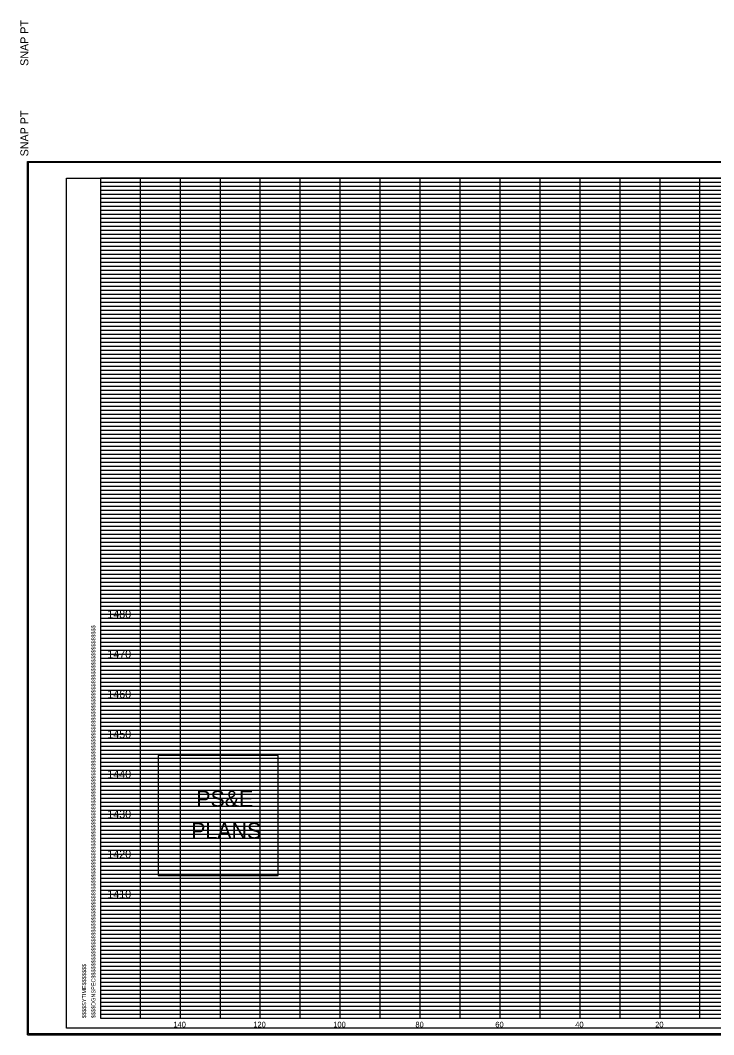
# Model space of a CAD drawing. Extents: x 980 to 2064, y 978 to 2267.
# Drawn here: x 979.9 to 1153.4, y 1255.9 to 1509.4 of the extents above; entities that cross this region are included whole.
import ezdxf

# ---------------------------------------------------------------- set-up
doc = ezdxf.new("R2010")
doc.units = 0
for name, color, linetype in [('Default', 7, 'Continuous'), ('DESIGN - SHEET - Corner Text', 7, 'Continuous'), ('DESIGN - SHEET - Light Grid', 7, 'Continuous'), ('DESIGN - SHEET - Linework', 7, 'Continuous'), ('DESIGN - SHEET - Plot Shape', 7, 'Continuous')]:
    doc.layers.add(name, color=color, linetype=linetype)

# ---------------------------------------------------------------- blocks, each defined once
blk = doc.blocks.new('XSTSHT')
at = {"layer": 'DESIGN - SHEET - Corner Text'}
blk.add_text('SNAP PT  ', height=0.2, rotation=90, dxfattribs=at).set_placement((-1.803, -2.194))

msp = doc.modelspace()

# ---------------------------------------------------------------- linework, layer by layer
at = {"layer": 'DESIGN - SHEET - Corner Text'}
msp.add_lwpolyline([(1014.45, 1325.68), (1014.45, 1295.68), (1044.45, 1295.68), (1044.45, 1325.68)], close=True, dxfattribs=at)
at = {"layer": 'DESIGN - SHEET - Light Grid'}
for p, q in [((1000, 1469), (1080, 1469)), ((1080, 1469), (1160, 1469)), ((1000, 1468), (1080, 1468)), ((1000, 1467), (1080, 1467)), ((1000, 1466), (1080, 1466)), ((1080, 1468), (1160, 1468)), ((1080, 1467), (1160, 1467)), ((1080, 1466), (1160, 1466)), ((1000, 1465), (1080, 1465)), ((1000, 1464), (1080, 1464)), ((1080, 1465), (1160, 1465)), ((1080, 1464), (1160, 1464)), ((1000, 1463), (1080, 1463)), ((1000, 1462), (1080, 1462)), ((1000, 1461), (1080, 1461)), ((1080, 1463), (1160, 1463)), ((1080, 1462), (1160, 1462)), ((1080, 1461), (1160, 1461)), ((1000, 1459), (1080, 1459)), ((1080, 1459), (1160, 1459)), ((1000, 1458), (1080, 1458)), ((1000, 1457), (1080, 1457)), ((1000, 1456), (1080, 1456)), ((1080, 1458), (1160, 1458)), ((1080, 1457), (1160, 1457)), ((1080, 1456), (1160, 1456)), ((1000, 1455), (1080, 1455)), ((1000, 1454), (1080, 1454)), ((1080, 1455), (1160, 1455)), ((1080, 1454), (1160, 1454)), ((1000, 1453), (1080, 1453)), ((1000, 1452), (1080, 1452)), ((1000, 1451), (1080, 1451)), ((1080, 1453), (1160, 1453)), ((1080, 1452), (1160, 1452)), ((1080, 1451), (1160, 1451)), ((1000, 1449), (1080, 1449)), ((1000, 1448), (1080, 1448)), ((1080, 1449), (1160, 1449)), ((1080, 1448), (1160, 1448)), ((1000, 1447), (1080, 1447)), ((1000, 1446), (1080, 1446)), ((1080, 1447), (1160, 1447)), ((1080, 1446), (1160, 1446)), ((1000, 1445), (1080, 1445)), ((1000, 1444), (1080, 1444)), ((1000, 1443), (1080, 1443)), ((1080, 1445), (1160, 1445)), ((1080, 1444), (1160, 1444)), ((1080, 1443), (1160, 1443)), ((1000, 1442), (1080, 1442)), ((1000, 1441), (1080, 1441)), ((1080, 1442), (1160, 1442)), ((1080, 1441), (1160, 1441)), ((1000, 1439), (1080, 1439)), ((1000, 1438), (1080, 1438)), ((1080, 1439), (1160, 1439)), ((1080, 1438), (1160, 1438)), ((1000, 1437), (1080, 1437)), ((1000, 1436), (1080, 1436)), ((1080, 1437), (1160, 1437)), ((1080, 1436), (1160, 1436)), ((1000, 1435), (1080, 1435)), ((1000, 1434), (1080, 1434)), ((1000, 1433), (1080, 1433)), ((1080, 1435), (1160, 1435)), ((1080, 1434), (1160, 1434)), ((1080, 1433), (1160, 1433)), ((1000, 1432), (1080, 1432)), ((1000, 1431), (1080, 1431)), ((1080, 1432), (1160, 1432)), ((1080, 1431), (1160, 1431)), ((1000, 1429), (1080, 1429)), ((1000, 1428), (1080, 1428)), ((1080, 1429), (1160, 1429)), ((1080, 1428), (1160, 1428)), ((1000, 1427), (1080, 1427)), ((1000, 1426), (1080, 1426)), ((1080, 1427), (1160, 1427)), ((1080, 1426), (1160, 1426)), ((1000, 1425), (1080, 1425)), ((1000, 1424), (1080, 1424)), ((1000, 1423), (1080, 1423)), ((1080, 1425), (1160, 1425)), ((1080, 1424), (1160, 1424)), ((1080, 1423), (1160, 1423)), ((1000, 1422), (1080, 1422)), ((1000, 1421), (1080, 1421)), ((1080, 1422), (1160, 1422)), ((1080, 1421), (1160, 1421)), ((1000, 1419), (1080, 1419)), ((1000, 1418), (1080, 1418)), ((1080, 1419), (1160, 1419)), ((1080, 1418), (1160, 1418)), ((1000, 1417), (1080, 1417)), ((1000, 1416), (1080, 1416)), ((1000, 1415), (1080, 1415)), ((1080, 1417), (1160, 1417)), ((1080, 1416), (1160, 1416)), ((1080, 1415), (1160, 1415)), ((1000, 1414), (1080, 1414)), ((1000, 1413), (1080, 1413)), ((1080, 1414), (1160, 1414)), ((1080, 1413), (1160, 1413)), ((1000, 1412), (1080, 1412)), ((1000, 1411), (1080, 1411)), ((1080, 1412), (1160, 1412)), ((1080, 1411), (1160, 1411)), ((1000, 1409), (1080, 1409)), ((1000, 1408), (1080, 1408)), ((1080, 1409), (1160, 1409)), ((1080, 1408), (1160, 1408)), ((1000, 1407), (1080, 1407)), ((1000, 1406), (1080, 1406)), ((1000, 1405), (1080, 1405)), ((1080, 1407), (1160, 1407)), ((1080, 1406), (1160, 1406)), ((1080, 1405), (1160, 1405)), ((1000, 1404), (1080, 1404)), ((1000, 1403), (1080, 1403)), ((1080, 1404), (1160, 1404)), ((1080, 1403), (1160, 1403)), ((1000, 1402), (1080, 1402)), ((1000, 1401), (1080, 1401)), ((1080, 1402), (1160, 1402)), ((1080, 1401), (1160, 1401)), ((1000, 1399), (1080, 1399)), ((1000, 1398), (1080, 1398)), ((1080, 1399), (1160, 1399)), ((1080, 1398), (1160, 1398)), ((1000, 1397), (1080, 1397)), ((1000, 1396), (1080, 1396)), ((1000, 1395), (1080, 1395)), ((1080, 1397), (1160, 1397)), ((1080, 1396), (1160, 1396)), ((1080, 1395), (1160, 1395)), ((1000, 1394), (1080, 1394)), ((1000, 1393), (1080, 1393)), ((1080, 1394), (1160, 1394)), ((1080, 1393), (1160, 1393)), ((1000, 1392), (1080, 1392)), ((1000, 1391), (1080, 1391)), ((1080, 1392), (1160, 1392)), ((1080, 1391), (1160, 1391)), ((1000, 1389), (1080, 1389)), ((1000, 1388), (1080, 1388)), ((1080, 1389), (1160, 1389)), ((1080, 1388), (1160, 1388)), ((1000, 1387), (1080, 1387)), ((1000, 1386), (1080, 1386)), ((1000, 1385), (1080, 1385)), ((1080, 1387), (1160, 1387)), ((1080, 1386), (1160, 1386)), ((1080, 1385), (1160, 1385)), ((1000, 1384), (1080, 1384)), ((1000, 1383), (1080, 1383)), ((1080, 1384), (1160, 1384)), ((1080, 1383), (1160, 1383)), ((1000, 1382), (1080, 1382)), ((1000, 1381), (1080, 1381)), ((1080, 1382), (1160, 1382)), ((1080, 1381), (1160, 1381)), ((1000, 1379), (1080, 1379)), ((1000, 1378), (1080, 1378)), ((1000, 1377), (1080, 1377)), ((1080, 1379), (1160, 1379)), ((1080, 1378), (1160, 1378)), ((1080, 1377), (1160, 1377)), ((1000, 1376), (1080, 1376)), ((1000, 1375), (1080, 1375)), ((1080, 1376), (1160, 1376)), ((1080, 1375), (1160, 1375)), ((1000, 1374), (1080, 1374)), ((1000, 1373), (1080, 1373)), ((1000, 1372), (1080, 1372)), ((1080, 1374), (1160, 1374)), ((1080, 1373), (1160, 1373)), ((1080, 1372), (1160, 1372)), ((1000, 1371), (1080, 1371)), ((1080, 1371), (1160, 1371)), ((1000, 1369), (1080, 1369)), ((1000, 1368), (1080, 1368)), ((1000, 1367), (1080, 1367)), ((1080, 1369), (1160, 1369)), ((1080, 1368), (1160, 1368)), ((1080, 1367), (1160, 1367)), ((1000, 1366), (1080, 1366)), ((1000, 1365), (1080, 1365)), ((1080, 1366), (1160, 1366)), ((1080, 1365), (1160, 1365)), ((1000, 1364), (1080, 1364)), ((1000, 1363), (1080, 1363)), ((1000, 1362), (1080, 1362)), ((1080, 1364), (1160, 1364)), ((1080, 1363), (1160, 1363)), ((1080, 1362), (1160, 1362)), ((1000, 1361), (1080, 1361)), ((1080, 1361), (1160, 1361)), ((1000, 1359), (1080, 1359)), ((1000, 1358), (1080, 1358)), ((1000, 1357), (1080, 1357)), ((1080, 1359), (1160, 1359)), ((1080, 1358), (1160, 1358)), ((1080, 1357), (1160, 1357)), ((1000, 1356), (1080, 1356)), ((1000, 1355), (1080, 1355)), ((1080, 1356), (1160, 1356)), ((1080, 1355), (1160, 1355)), ((1000, 1354), (1080, 1354)), ((1000, 1353), (1080, 1353)), ((1000, 1352), (1080, 1352)), ((1080, 1354), (1160, 1354)), ((1080, 1353), (1160, 1353)), ((1080, 1352), (1160, 1352)), ((1000, 1351), (1080, 1351)), ((1080, 1351), (1160, 1351)), ((1000, 1349), (1080, 1349)), ((1000, 1348), (1080, 1348)), ((1000, 1347), (1080, 1347)), ((1080, 1349), (1160, 1349)), ((1080, 1348), (1160, 1348)), ((1080, 1347), (1160, 1347)), ((1000, 1346), (1080, 1346)), ((1000, 1345), (1080, 1345)), ((1000, 1344), (1080, 1344)), ((1080, 1346), (1160, 1346)), ((1080, 1345), (1160, 1345)), ((1080, 1344), (1160, 1344)), ((1000, 1343), (1080, 1343)), ((1000, 1342), (1080, 1342)), ((1080, 1343), (1160, 1343)), ((1080, 1342), (1160, 1342)), ((1000, 1341), (1080, 1341)), ((1000, 1339), (1080, 1339)), ((1080, 1341), (1160, 1341)), ((1080, 1339), (1160, 1339)), ((1000, 1338), (1080, 1338)), ((1000, 1337), (1080, 1337)), ((1080, 1338), (1160, 1338)), ((1080, 1337), (1160, 1337)), ((1000, 1336), (1080, 1336)), ((1000, 1335), (1080, 1335)), ((1000, 1334), (1080, 1334)), ((1080, 1336), (1160, 1336)), ((1080, 1335), (1160, 1335)), ((1080, 1334), (1160, 1334)), ((1000, 1333), (1080, 1333)), ((1000, 1332), (1080, 1332)), ((1080, 1333), (1160, 1333)), ((1080, 1332), (1160, 1332)), ((1000, 1331), (1080, 1331)), ((1000, 1329), (1080, 1329)), ((1080, 1331), (1160, 1331)), ((1080, 1329), (1160, 1329)), ((1000, 1328), (1080, 1328)), ((1000, 1327), (1080, 1327)), ((1080, 1328), (1160, 1328)), ((1080, 1327), (1160, 1327)), ((1000, 1326), (1080, 1326)), ((1000, 1325), (1080, 1325)), ((1000, 1324), (1080, 1324)), ((1080, 1326), (1160, 1326)), ((1080, 1325), (1160, 1325)), ((1080, 1324), (1160, 1324)), ((1000, 1323), (1080, 1323)), ((1000, 1322), (1080, 1322)), ((1080, 1323), (1160, 1323)), ((1080, 1322), (1160, 1322)), ((1000, 1321), (1080, 1321)), ((1000, 1319), (1080, 1319)), ((1080, 1321), (1160, 1321)), ((1080, 1319), (1160, 1319)), ((1000, 1318), (1080, 1318)), ((1000, 1317), (1080, 1317)), ((1080, 1318), (1160, 1318)), ((1080, 1317), (1160, 1317)), ((1000, 1316), (1080, 1316)), ((1000, 1315), (1080, 1315)), ((1000, 1314), (1080, 1314)), ((1080, 1316), (1160, 1316)), ((1080, 1315), (1160, 1315)), ((1080, 1314), (1160, 1314)), ((1000, 1313), (1080, 1313)), ((1000, 1312), (1080, 1312)), ((1080, 1313), (1160, 1313)), ((1080, 1312), (1160, 1312)), ((1000, 1311), (1080, 1311)), ((1000, 1309), (1080, 1309)), ((1080, 1311), (1160, 1311)), ((1080, 1309), (1160, 1309)), ((1000, 1308), (1080, 1308)), ((1000, 1307), (1080, 1307)), ((1000, 1306), (1080, 1306)), ((1080, 1308), (1160, 1308)), ((1080, 1307), (1160, 1307)), ((1080, 1306), (1160, 1306)), ((1000, 1305), (1080, 1305)), ((1000, 1304), (1080, 1304)), ((1080, 1305), (1160, 1305)), ((1080, 1304), (1160, 1304)), ((1000, 1303), (1080, 1303)), ((1000, 1302), (1080, 1302)), ((1000, 1301), (1080, 1301)), ((1080, 1303), (1160, 1303)), ((1080, 1302), (1160, 1302)), ((1080, 1301), (1160, 1301)), ((1000, 1299), (1080, 1299)), ((1080, 1299), (1160, 1299)), ((1000, 1298), (1080, 1298)), ((1000, 1297), (1080, 1297)), ((1000, 1296), (1080, 1296)), ((1080, 1298), (1160, 1298)), ((1080, 1297), (1160, 1297)), ((1080, 1296), (1160, 1296)), ((1000, 1295), (1080, 1295)), ((1000, 1294), (1080, 1294)), ((1080, 1295), (1160, 1295)), ((1080, 1294), (1160, 1294)), ((1000, 1293), (1080, 1293)), ((1000, 1292), (1080, 1292)), ((1000, 1291), (1080, 1291)), ((1080, 1293), (1160, 1293)), ((1080, 1292), (1160, 1292)), ((1080, 1291), (1160, 1291)), ((1000, 1289), (1080, 1289)), ((1080, 1289), (1160, 1289)), ((1000, 1288), (1080, 1288)), ((1000, 1287), (1080, 1287)), ((1000, 1286), (1080, 1286)), ((1080, 1288), (1160, 1288)), ((1080, 1287), (1160, 1287)), ((1080, 1286), (1160, 1286)), ((1000, 1285), (1080, 1285)), ((1000, 1284), (1080, 1284)), ((1080, 1285), (1160, 1285)), ((1080, 1284), (1160, 1284)), ((1000, 1283), (1080, 1283)), ((1000, 1282), (1080, 1282)), ((1000, 1281), (1080, 1281)), ((1080, 1283), (1160, 1283)), ((1080, 1282), (1160, 1282)), ((1080, 1281), (1160, 1281)), ((1000, 1279), (1080, 1279)), ((1080, 1279), (1160, 1279)), ((1000, 1278), (1080, 1278)), ((1000, 1277), (1080, 1277)), ((1000, 1276), (1080, 1276)), ((1080, 1278), (1160, 1278)), ((1080, 1277), (1160, 1277)), ((1080, 1276), (1160, 1276)), ((1000, 1275), (1080, 1275)), ((1000, 1274), (1080, 1274)), ((1000, 1273), (1080, 1273)), ((1080, 1275), (1160, 1275)), ((1080, 1274), (1160, 1274)), ((1080, 1273), (1160, 1273)), ((1000, 1272), (1080, 1272)), ((1000, 1271), (1080, 1271)), ((1080, 1272), (1160, 1272)), ((1080, 1271), (1160, 1271)), ((1000, 1269), (1080, 1269)), ((1000, 1268), (1080, 1268)), ((1080, 1269), (1160, 1269)), ((1080, 1268), (1160, 1268)), ((1000, 1267), (1080, 1267)), ((1000, 1266), (1080, 1266)), ((1080, 1267), (1160, 1267)), ((1080, 1266), (1160, 1266)), ((1000, 1265), (1080, 1265)), ((1000, 1264), (1080, 1264)), ((1000, 1263), (1080, 1263)), ((1080, 1265), (1160, 1265)), ((1080, 1264), (1160, 1264)), ((1080, 1263), (1160, 1263)), ((1000, 1262), (1080, 1262)), ((1000, 1261), (1080, 1261)), ((1080, 1262), (1160, 1262)), ((1080, 1261), (1160, 1261))]:
    msp.add_line(p, q, dxfattribs=at)
at = {"layer": 'DESIGN - SHEET - Linework'}
for p, q in [((981.77, 1255.86), (981.77, 1474.14)), ((981.77, 1474.14), (1322.17, 1474.14)), ((1010, 1260), (1010, 1470)), ((1020, 1260), (1020, 1470)), ((1030, 1260), (1030, 1470)), ((1040, 1260), (1040, 1470)), ((1050, 1260), (1050, 1470)), ((1060, 1260), (1060, 1470)), ((1070, 1260), (1070, 1470)), ((1080, 1260), (1080, 1470)), ((1090, 1260), (1090, 1470)), ((1100, 1260), (1100, 1470)), ((1110, 1260), (1110, 1470)), ((1120, 1260), (1120, 1470)), ((1130, 1260), (1130, 1470)), ((1140, 1260), (1140, 1470)), ((1150, 1260), (1150, 1470)), ((1000, 1460), (1280, 1460)), ((1000, 1450), (1320, 1450)), ((1000, 1440), (1320, 1440)), ((1000, 1430), (1320, 1430)), ((1000, 1420), (1320, 1420)), ((1000, 1410), (1320, 1410)), ((1000, 1400), (1320, 1400)), ((1000, 1390), (1320, 1390)), ((1000, 1380), (1320, 1380)), ((1000, 1370), (1320, 1370)), ((1000, 1360), (1320, 1360)), ((1000, 1350), (1320, 1350)), ((1000, 1340), (1320, 1340)), ((1000, 1330), (1320, 1330)), ((1000, 1320), (1320, 1320)), ((1000, 1310), (1320, 1310)), ((1000, 1300), (1320, 1300)), ((1000, 1290), (1320, 1290)), ((1000, 1280), (1320, 1280)), ((1000, 1270), (1320, 1270)), ((981.77, 1255.86), (1322.17, 1255.86))]:
    msp.add_line(p, q, dxfattribs=at)
msp.add_lwpolyline([(1000, 1470), (1000, 1260), (1320, 1260), (1320, 1470), (1000, 1470)], dxfattribs=at)
at = {"layer": 'DESIGN - SHEET - Plot Shape'}
for points in [[(981.97, 1473.94), (1321.97, 1473.94), (1321.97, 1256.06), (981.97, 1256.06)], [(991.5, 1470), (1320, 1470), (1320, 1257.5), (991.5, 1257.5)]]:
    msp.add_lwpolyline(points, close=True, dxfattribs=at)

# ---------------------------------------------------------------- block references
at = {"layer": 'Default', "xscale": 10, "yscale": 10}
msp.add_blockref('XSTSHT', (1000, 1520), dxfattribs=at)

# ---------------------------------------------------------------- texts
at = {"layer": 'Default'}
for s, height, p in [('     1480     ', 2, (998.01, 1360)), ('     1470     ', 2, (998.01, 1350)), ('     1460     ', 2, (998.01, 1340)), ('     1450     ', 2, (998.01, 1330)), ('     1440     ', 2, (998.01, 1320)), ('     1430     ', 2, (998.01, 1310)), ('     1420     ', 2, (998.01, 1300)), ('     1410     ', 2, (998.01, 1290)), ('     140     ', 1.4, (1015.65, 1257.7)), ('     120     ', 1.4, (1035.65, 1257.7)), ('     100     ', 1.4, (1055.65, 1257.7)), ('     80     ', 1.4, (1076.2, 1257.7)), ('     60     ', 1.4, (1096.2, 1257.7)), ('     40     ', 1.4, (1116.2, 1257.7)), ('     20     ', 1.4, (1136.2, 1257.7))]:
    msp.add_text(s, height=height, dxfattribs=at).set_placement(p)
at = {"layer": 'DESIGN - SHEET - Corner Text'}
for s, height, p in [('  SNAP PT', 2, (981.97, 1473.94)), ('$$$$DGNSPEC$$$$$$$$$$$$$$$$$$$$$$$$$$$$$$$$$$$$$$$$$$$$$$$$$$$$$$$$$$$$$$$$$$$$$$$$$$$$$$$$$$$$$$$$$$$$$$$$$$$$$$$$$$$$$$$$$$$', 1.00002, (998.74, 1260)), ('$$$$SYTIME$$$$$$$', 1, (996.42, 1260))]:
    msp.add_text(s, height=height, rotation=90, dxfattribs=at).set_placement(p)
for s, p in [('PS&E', (1023.97, 1312.86)), ('PLANS', (1022.68, 1304.86))]:
    msp.add_text(s, height=4, dxfattribs=at).set_placement(p)

doc.saveas('drawing.dxf')
